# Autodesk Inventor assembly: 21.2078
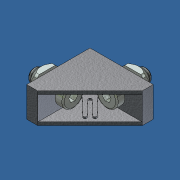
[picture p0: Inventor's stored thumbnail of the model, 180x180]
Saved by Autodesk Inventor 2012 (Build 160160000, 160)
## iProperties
Created: 2012-10
Part Number: 21.2078
Document SubType Name: Assembly
Designer: Administrator
Description: Angle 19 GD-Z
Stock Number: 21.2078 Angle 19 GD-Z
Author: Administrator
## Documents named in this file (4)
- C:\Andys Backup Data\ANDY'S INVENTOR\INVENTOR LIBRARIES\PARTS LIBRARY\FASTENING ELEMENTS\21.2078 Angle 19 GD-Z.iam
- C:\Andys Backup Data\ANDY'S INVENTOR\INVENTOR LIBRARIES\PARTS LIBRARY\FASTENING ELEMENTS\SUBCOMPONENTS\21.2078_1 Angle 19.ipt
- C:\Andys Backup Data\ANDY'S INVENTOR\INVENTOR LIBRARIES\PARTS LIBRARY\FASTENING ELEMENTS\SCREWS CAP\21.1202 M8X20.ipt
- C:\Andys Backup Data\ANDY'S INVENTOR\INVENTOR LIBRARIES\PARTS LIBRARY\FASTENING ELEMENTS\NUTS\21.1351 M8 SQUARE NUT.ipt
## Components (5 placed, 3 different names)
1. 21.2078_1 Angle 19:1 — Mate:1, Mate:2, Mate:3, Mate:4, Mate:5, Mate:6, Mate:8, Mate:9, Angle:1, Angle:2
2. 21.1202  M8 x 20:1 — Mate:1, Mate:2, Mate:5, Mate:10
3. 21.1202  M8 x 20:2 — Mate:3, Mate:4, Mate:6, Mate:7
4. 21.1351 M8 SQUARE NUT:1 — Mate:7, Mate:8, Angle:2
5. 21.1351 M8 SQUARE NUT:2 — Mate:9, Mate:10, Angle:1
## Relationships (12: Mate 10, Angle 2)
- Mate:1: 21.2078_1 Angle 19:1 ↔ 21.1202  M8 x 20:1
- Mate:2: 21.2078_1 Angle 19:1 ↔ 21.1202  M8 x 20:1
- Mate:3: 21.2078_1 Angle 19:1 ↔ 21.1202  M8 x 20:2
- Mate:4: 21.2078_1 Angle 19:1 ↔ 21.1202  M8 x 20:2
- Mate:5: 21.2078_1 Angle 19:1 ↔ 21.1202  M8 x 20:1
- Mate:6: 21.2078_1 Angle 19:1 ↔ 21.1202  M8 x 20:2
- Mate:7: 21.1202  M8 x 20:2 ↔ 21.1351 M8 SQUARE NUT:1
- Mate:8: 21.2078_1 Angle 19:1 ↔ 21.1351 M8 SQUARE NUT:1
- Mate:9: 21.2078_1 Angle 19:1 ↔ 21.1351 M8 SQUARE NUT:2
- Mate:10: 21.1202  M8 x 20:1 ↔ 21.1351 M8 SQUARE NUT:2
- Angle:1: 21.2078_1 Angle 19:1 ↔ 21.1351 M8 SQUARE NUT:2
- Angle:2: 21.2078_1 Angle 19:1 ↔ 21.1351 M8 SQUARE NUT:1
